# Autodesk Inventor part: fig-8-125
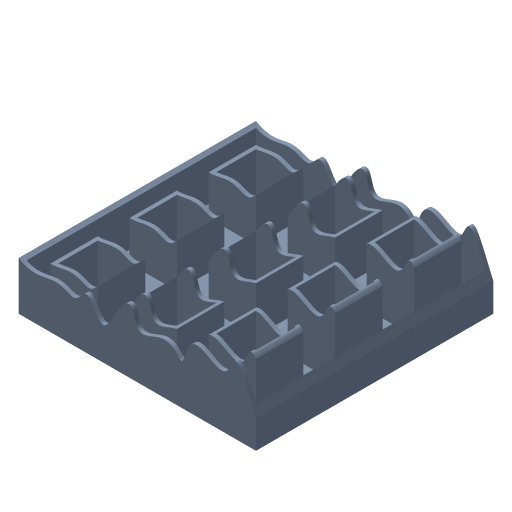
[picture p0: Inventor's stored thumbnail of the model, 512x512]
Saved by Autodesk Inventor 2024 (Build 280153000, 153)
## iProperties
Shininess: 64.0
Length Units: 11269
Angle Units: 11279
Time Units: 11290
Mass Units: 11283
Length Display Precision: 3
Angle Display Precision: 2
Compacted: True
Part Number: fig-8-125
Document SubType Name: Modeling
Created: 2002-12
Designer: deepak
Density: 1 g/cm^3
Material: Generic
Appearance: Light Steel Blue
Density: 0.0
Volumn: 0.0
Area: 0.0
PropertySet Name: Model Information
Control State: 0
Master: False
Checked Out: False
Author: deepak
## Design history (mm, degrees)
sketch "Sketch1"
  geometry: L1 (-32.188, 30.089)-(27.812, 30.089); L2 (27.812, 30.089)-(27.812, -29.911); L3 (27.812, -29.911)-(-32.188, -29.911); L4 (-32.188, -29.911)-(-32.188, 30.089)
  constraints: 8 end point, 2 parallel, 1 horizontal, 1 perpendicular
  dimensions: "d0" = 60 distance of L1.start L1.end; "d1" = 60 distance of L3.end L1.start
extrude "Extrusion1" new body sketch "Sketch1" stored distance "d2" = 20; taper "d3" = 0 deg
sketch "Sketch5"
  geometry: L1 (-27.812, 30.089)-(32.188, 30.089) reference; L2 (-27.812, -29.911)-(-27.812, 30.089) reference; L3 (-22.812, 25.089)-(-12.812, 25.089); L4 (-12.812, 25.089)-(-12.812, 15.089); L5 (-12.812, 15.089)-(-22.812, 15.089); L6 (-22.812, 15.089)-(-22.812, 25.089)
  constraints: 8 end point, 2 parallel, 1 horizontal, 1 perpendicular
  dimensions: "d8" = 10 distance of L3.start L3.end; "d9" = 10 distance of L5.end L3.start; "d10" = 5 distance between parallel lines of L2 L6; "d11" = 5 distance between parallel lines of L1 L3
extrude "Extrusion2" cut sketch "Sketch5" distance "d12" = 50; taper "d13" = 0 deg
pattern_linear "Rectangular Pattern1" dims "d16" = 20, "d19" = 20
shell "Shell2" dims "d21" = 1
sketch "Sketch2"
  geometry: 17 further points
  constraints: 17 other
extrude_surface "ExtrusionSrf1" sketch "Sketch2" dims "d4" = 70, "d5" = 0
split "Split2"
body "Solid1"
body "Srf1"
